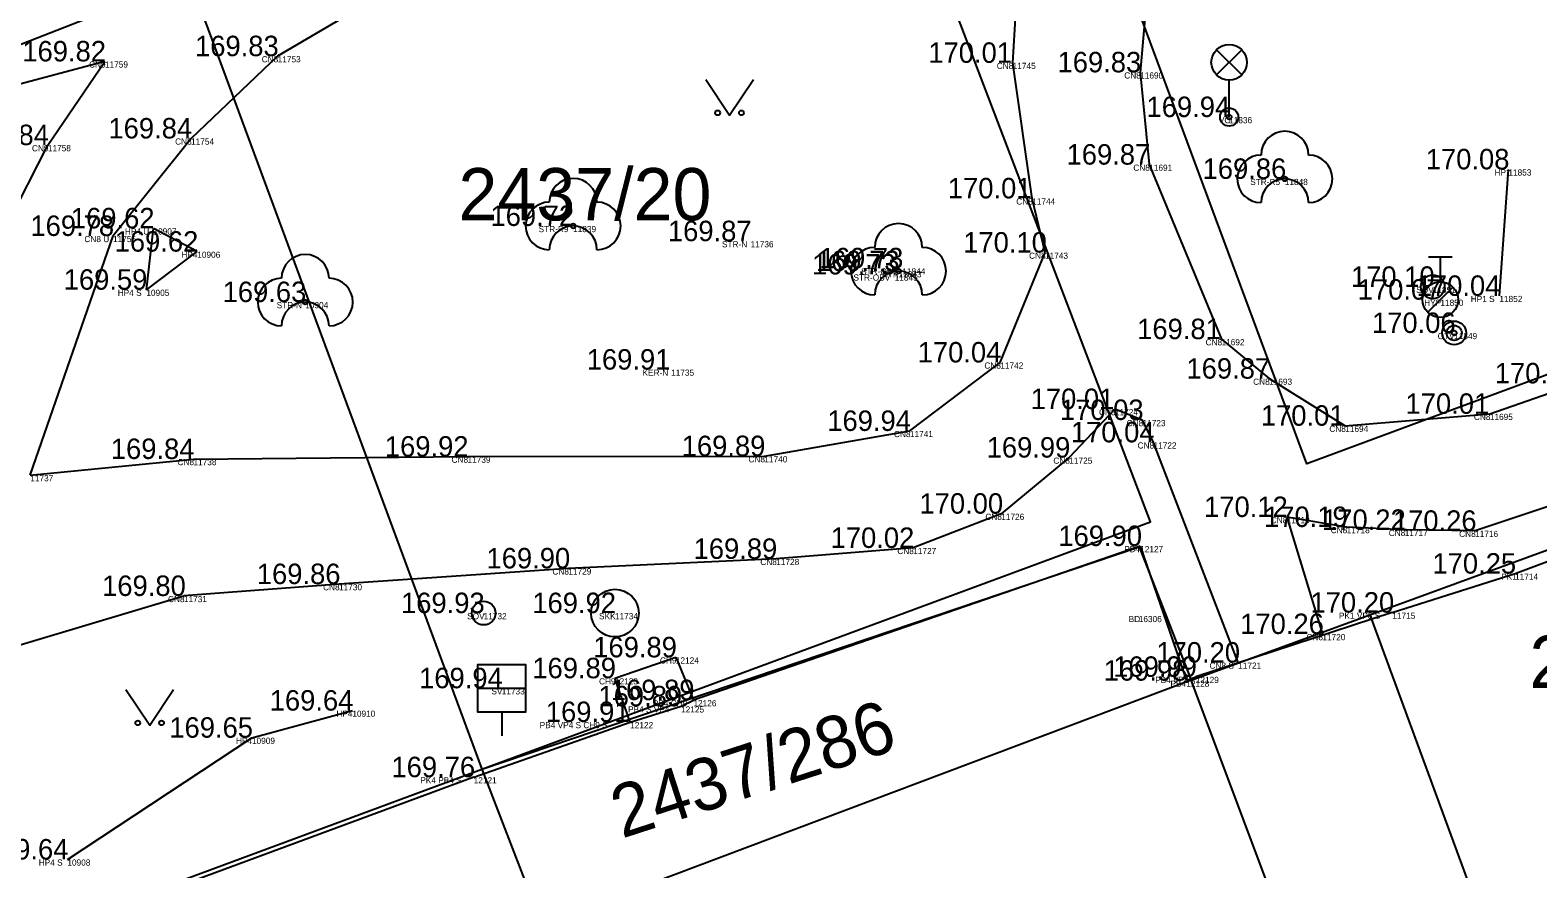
# Model space of a CAD drawing. Extents: x -566117 to -565580, y -1202428 to -1201938.
# Drawn here: x -565973.6 to -565941.91, y -1202276.24 to -1202258.6 of the extents above; entities that cross this region are included whole.
import ezdxf

# ---------------------------------------------------------------- set-up
doc = ezdxf.new("R2010")
doc.units = 0
for name, color, linetype in [('Bod', 7, 'Continuous'), ('CIZÍ_NADZEM', 7, 'Continuous'), ('Implicitní', 7, 'Continuous'), ('Kanalizace', 7, 'Continuous'), ('Katastr', 7, 'Continuous'), ('Kod', 7, 'Continuous'), ('Oplocení', 7, 'Continuous'), ('Voda', 7, 'Continuous'), ('Výška', 7, 'Continuous'), ('ZELEŇ', 7, 'Continuous'), ('ZN_KULTUR', 7, 'Continuous'), ('Zpevněné plohy', 7, 'Continuous'), ('Číslo', 7, 'Continuous')]:
    doc.layers.add(name, color=color, linetype=linetype)

# ---------------------------------------------------------------- blocks, each defined once
blk = doc.blocks.new('A$C69D74C1E')
at = {"layer": 'Katastr'}
for p, q in [((94.11, -187.55), (100.82, -205.7)), ((119.49, -202.46), (128.42, -199.18)), ((115.73, -203.83), (119.49, -202.46)), ((119.49, -202.46), (128.38, -226.66)), ((115.73, -203.83), (102.08, -208.97)), ((125.13, -228.9), (115.73, -203.83)), ((86.57, -210.98), (100.82, -205.7)), ((100.82, -205.7), (102.08, -208.97))]:
    blk.add_line(p, q, dxfattribs=at)
for points in [[(132.68, -193.9), (118.16, -199.28), (104.08, -161.33)], [(100.82, -205.7), (114.88, -200.5), (107.96, -182.37)], [(100.82, -205.7), (114.64, -201.03), (115.73, -203.83)]]:
    blk.add_lwpolyline(points, dxfattribs=at)
for s, p in [('2437/20', (100.33, -194.163)), ('2437/287', (122.843, -203.993))]:
    blk.add_text(s, height=1.1, dxfattribs=at).set_placement(p)
blk.add_text('2437/286', height=1.1, rotation=18, dxfattribs=at).set_placement((103.766, -207.164))
blk = doc.blocks.new('SV')
at = {"layer": 'Voda'}
blk.add_circle((0, 0), 0.25, dxfattribs=at)
blk = doc.blocks.new('OS')
at = {"layer": 'Voda'}
for radius in [0.25, 0.158, 0.05]:
    blk.add_circle((0, 0), radius, dxfattribs=at)
blk = doc.blocks.new('SAV')
at = {"layer": 'Voda'}
blk.add_line((0, -0.5), (0, -1), dxfattribs=at)
for points in [[(-0.5, 0), (-0.5, 0.5), (0.5, 0.5), (0.5, 0)], [(0.5, 0), (0.5, -0.5), (-0.5, -0.5), (-0.5, 0), (0.5, 0)]]:
    blk.add_lwpolyline(points, dxfattribs=at)
blk = doc.blocks.new('STROM')
at = {"layer": 'ZELEŇ'}
blk.add_circle((0, 0), 0.05, dxfattribs=at)
for centre, start, end in [((0, 0.5), 0, 180), ((-0.5, 0), 90, 270), ((0.5, 0), 270, 90), ((0, -0.5), 0, 180)]:
    blk.add_arc(centre, 0.5, start, end, dxfattribs=at)
blk = doc.blocks.new('SAK')
at = {"layer": 'Kanalizace'}
blk.add_circle((0, 0), 0.5, dxfattribs=at)
blk = doc.blocks.new('LA')
at = {"layer": 'CIZÍ_NADZEM'}
for p, q in [((-0.265, 1.415), (0.265, 0.885)), ((-0.265, 0.885), (0.265, 1.415)), ((0, 0), (0, 0.775))]:
    blk.add_line(p, q, dxfattribs=at)
for centre, radius in [((0, 1.15), 0.375), ((0, 0), 0.19), ((0, 0), 0.05)]:
    blk.add_circle(centre, radius, dxfattribs=at)
blk = doc.blocks.new('HYP')
at = {"layer": 'CIZÍ_NADZEM'}
for p, q in [((-0.25, 0.899), (0.25, 0.899)), ((0, 0.375), (0, 0.899)), ((-0.265, -0.265), (0.265, 0.265))]:
    blk.add_line(p, q, dxfattribs=at)
blk.add_circle((0, 0), 0.375, dxfattribs=at)
blk = doc.blocks.new('POINT_DISPLAY')
at = {"layer": 'Implicitní'}
blk.add_line((0, 0), (0, 0), dxfattribs=at)
blk = doc.blocks.new('3.140_2')
at = {"layer": 'ZN_KULTUR'}
blk.add_lwpolyline([(-1, 1.5), (0, 0), (1, 1.5)], dxfattribs=at)
for centre in [(-0.5, 0.1), (0.5, 0.1)]:
    blk.add_circle(centre, 0.1, dxfattribs=at)

msp = doc.modelspace()

# ---------------------------------------------------------------- linework, layer by layer
at = {"layer": 'Oplocení'}
for p, q in [((-565942.39, -1202270.03), (-565937.78, -1202268.28)), ((-565950.27, -1202269.45), (-565959.66, -1202272.69)), ((-565950.27, -1202269.45), (-565949.3, -1202272.28)), ((-565944.97, -1202270.85), (-565942.39, -1202270.03)), ((-565944.97, -1202270.85), (-565949.1, -1202272.2)), ((-565949.3, -1202272.28), (-565949.1, -1202272.2)), ((-565960.99, -1202273.15), (-565959.92, -1202272.82)), ((-565959.92, -1202272.82), (-565959.66, -1202272.69)), ((-565964.28, -1202274.31), (-565960.99, -1202273.15)), ((-565964.28, -1202274.31), (-565972.48, -1202277.34))]:
    msp.add_line(p, q, dxfattribs=at)
at = {"layer": 'ZELEŇ'}
for p, q in [((-565942.72, -1202264.19), (-565942.53, -1202261.53)), ((-565971.16, -1202264.06), (-565971.01, -1202262.77)), ((-565970.09, -1202263.26), (-565971.01, -1202262.77)), ((-565971.16, -1202264.06), (-565970.09, -1202263.26)), ((-565968.94, -1202273.48), (-565966.83, -1202272.91)), ((-565972.82, -1202276.04), (-565968.94, -1202273.48))]:
    msp.add_line(p, q, dxfattribs=at)
at = {"layer": 'Zpevněné plohy'}
for p, q in [((-565949.99, -1202256.29), (-565950.27, -1202259.49)), ((-565952.95, -1202259.29), (-565952.79, -1202256.63)), ((-565965.97, -1202257.72), (-565968.4, -1202259.15)), ((-565978, -1202260.55), (-565971.32, -1202257.92)), ((-565972.03, -1202259.26), (-565974.74, -1202259.98)), ((-565973.23, -1202261.02), (-565972.03, -1202259.26)), ((-565968.4, -1202259.15), (-565970.22, -1202260.88)), ((-565952.54, -1202262.14), (-565952.95, -1202259.29)), ((-565950.27, -1202259.49), (-565950.08, -1202261.43)), ((-565970.22, -1202260.88), (-565971.86, -1202262.93)), ((-565974.08, -1202262.69), (-565973.23, -1202261.02)), ((-565950.08, -1202261.43), (-565948.56, -1202265.1)), ((-565952.27, -1202263.28), (-565952.54, -1202262.14)), ((-565973.6, -1202267.96), (-565971.86, -1202262.93)), ((-565953.21, -1202265.59), (-565952.27, -1202263.28)), ((-565948.56, -1202265.1), (-565947.56, -1202265.93)), ((-565955.11, -1202267.03), (-565953.21, -1202265.59)), ((-565947.56, -1202265.93), (-565945.96, -1202266.92)), ((-565942.92, -1202266.67), (-565941.08, -1202266.03)), ((-565950.8, -1202266.57), (-565951.76, -1202267.59)), ((-565950.22, -1202266.8), (-565950.8, -1202266.57)), ((-565949.99, -1202267.27), (-565950.22, -1202266.8)), ((-565945.96, -1202266.92), (-565942.92, -1202266.67)), ((-565958.17, -1202267.56), (-565955.11, -1202267.03)), ((-565964.41, -1202267.57), (-565958.17, -1202267.56)), ((-565948.21, -1202271.9), (-565949.99, -1202267.27)), ((-565938.04, -1202267.39), (-565943.23, -1202269.13)), ((-565973.6, -1202267.96), (-565970.17, -1202267.62)), ((-565970.17, -1202267.62), (-565964.41, -1202267.57)), ((-565951.76, -1202267.59), (-565953.19, -1202268.77)), ((-565953.19, -1202268.77), (-565955.04, -1202269.49)), ((-565947.19, -1202268.84), (-565946.44, -1202271.3)), ((-565945.93, -1202269.05), (-565947.19, -1202268.84)), ((-565944.71, -1202269.11), (-565945.93, -1202269.05)), ((-565943.23, -1202269.13), (-565944.71, -1202269.11)), ((-565957.92, -1202269.72), (-565962.29, -1202269.92)), ((-565955.04, -1202269.49), (-565957.92, -1202269.72)), ((-565962.29, -1202269.92), (-565967.11, -1202270.25)), ((-565967.11, -1202270.25), (-565970.37, -1202270.5)), ((-565961.31, -1202272.23), (-565960.03, -1202271.79)), ((-565960.03, -1202271.79), (-565959.66, -1202272.69)), ((-565960.99, -1202273.15), (-565961.31, -1202272.23))]:
    msp.add_line(p, q, dxfattribs=at)
msp.add_lwpolyline([(-565976.15, -1202272.67), (-565974.64, -1202271.77), (-565970.37, -1202270.5)], dxfattribs=at)

# ---------------------------------------------------------------- block references
at = {"layer": 'Bod'}
for p in [(-565972.03, -1202259.26), (-565968.4, -1202259.15), (-565952.95, -1202259.29), (-565950.27, -1202259.49), (-565948.4, -1202260.43), (-565970.22, -1202260.88), (-565973.23, -1202261.02), (-565950.08, -1202261.43), (-565942.53, -1202261.53), (-565947.23, -1202261.73), (-565952.54, -1202262.14), (-565971.01, -1202262.77), (-565962.19, -1202262.72), (-565971.86, -1202262.93), (-565958.46, -1202263.04), (-565970.09, -1202263.26), (-565952.27, -1202263.28), (-565955.43, -1202263.74), (-565955.35, -1202263.67), (-565955.27, -1202263.61), (-565971.16, -1202264.06), (-565944.12, -1202264), (-565967.82, -1202264.32), (-565943.96, -1202264.27), (-565942.72, -1202264.19), (-565943.67, -1202264.97), (-565948.56, -1202265.1), (-565953.21, -1202265.59), (-565960.13, -1202265.74), (-565947.56, -1202265.93), (-565950.8, -1202266.57), (-565950.22, -1202266.8), (-565945.96, -1202266.92), (-565942.92, -1202266.67), (-565955.11, -1202267.03), (-565958.17, -1202267.56), (-565949.99, -1202267.27), (-565970.17, -1202267.62), (-565964.41, -1202267.57), (-565951.76, -1202267.59), (-565973.6, -1202267.96), (-565953.19, -1202268.77), (-565947.19, -1202268.84), (-565945.93, -1202269.05), (-565944.71, -1202269.11), (-565943.23, -1202269.13), (-565950.27, -1202269.45), (-565957.92, -1202269.72), (-565955.04, -1202269.49), (-565962.29, -1202269.92), (-565942.39, -1202270.03), (-565967.11, -1202270.25), (-565970.37, -1202270.5), (-565964.07, -1202270.86), (-565961.31, -1202270.86), (-565950.3, -1202270.92), (-565944.97, -1202270.85), (-565946.44, -1202271.3), (-565960.03, -1202271.79), (-565948.21, -1202271.9), (-565961.31, -1202272.23), (-565949.3, -1202272.28), (-565949.1, -1202272.2), (-565963.69, -1202272.44), (-565966.83, -1202272.91), (-565959.92, -1202272.82), (-565959.66, -1202272.69), (-565960.99, -1202273.15), (-565968.94, -1202273.48), (-565964.28, -1202274.31), (-565972.82, -1202276.04)]:
    msp.add_blockref('POINT_DISPLAY', p, dxfattribs=at)
at = {"layer": 'CIZÍ_NADZEM'}
for name, p in [('LA', (-565948.4, -1202260.43)), ('HYP', (-565943.96, -1202264.27))]:
    msp.add_blockref(name, p, dxfattribs=at)
at = {"layer": 'Implicitní'}
msp.add_blockref('A$C69D74C1E', (-566064.93, -1202068.44), dxfattribs=at)
at = {"layer": 'Kanalizace'}
msp.add_blockref('SAK', (-565961.31, -1202270.86), dxfattribs=at)
at = {"layer": 'Voda'}
for name, p in [('SV', (-565944.12, -1202264)), ('OS', (-565943.67, -1202264.97)), ('SV', (-565964.07, -1202270.86))]:
    msp.add_blockref(name, p, dxfattribs=at)
at = {"layer": 'Voda', "xscale": 0.9999953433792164, "yscale": 0.9999953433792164}
msp.add_blockref('SAV', (-565963.69, -1202272.44), dxfattribs=at)
at = {"layer": 'ZELEŇ'}
for p in [(-565947.23, -1202261.73), (-565962.19, -1202262.72), (-565955.35, -1202263.67), (-565967.82, -1202264.32)]:
    msp.add_blockref('STROM', p, dxfattribs=at)
at = {"layer": 'ZN_KULTUR', "xscale": 0.5, "yscale": 0.5}
for p in [(-565958.901, -1202260.391), (-565971.09, -1202273.218)]:
    msp.add_blockref('3.140_2', p, dxfattribs=at)

# ---------------------------------------------------------------- texts
at = {"layer": 'Kod'}
for s, p in [('CN9', (-565972.365, -1202259.39)), ('CN8', (-565968.735, -1202259.28)), ('CN8', (-565953.285, -1202259.42)), ('CN8', (-565950.605, -1202259.62)), ('VO', (-565948.616, -1202260.56)), ('CN8', (-565970.555, -1202261.01)), ('CN9', (-565973.565, -1202261.15)), ('CN8', (-565950.415, -1202261.56)), ('HP1', (-565942.822, -1202261.66)), ('STR-R5', (-565947.957, -1202261.86)), ('CN8', (-565952.875, -1202262.27)), ('HP4 U', (-565971.612, -1202262.9)), ('STR-R9', (-565962.915, -1202262.85)), ('CN8 U', (-565972.462, -1202263.06)), ('STR-N', (-565959.061, -1202263.17)), ('HP4', (-565970.425, -1202263.39)), ('CN8', (-565952.605, -1202263.41)), ('STR-OBV', (-565956.297, -1202263.87)), ('STR-OBV', (-565956.137, -1202263.74)), ('STR', (-565955.691, -1202263.8)), ('HP4 S', (-565971.762, -1202264.19)), ('SOV', (-565944.467, -1202264.13)), ('STR-N', (-565968.421, -1202264.45)), ('HYP', (-565944.301, -1202264.4)), ('HP1 S', (-565943.322, -1202264.32)), ('OTV', (-565944.017, -1202265.1)), ('CN8', (-565948.895, -1202265.23)), ('CN8', (-565953.545, -1202265.72)), ('KER-N', (-565960.731, -1202265.87)), ('CN8', (-565947.895, -1202266.06)), ('CN8', (-565951.135, -1202266.7)), ('CN8', (-565950.555, -1202266.93)), ('CN8', (-565946.295, -1202267.05)), ('CN8', (-565943.255, -1202266.8)), ('CN8', (-565955.445, -1202267.16)), ('CN8', (-565958.505, -1202267.69)), ('CN8', (-565950.325, -1202267.4)), ('CN8', (-565970.505, -1202267.75)), ('CN8', (-565964.745, -1202267.7)), ('CN8', (-565952.095, -1202267.72)), ('CN8', (-565953.525, -1202268.9)), ('CN8', (-565947.525, -1202268.97)), ('CN8', (-565946.265, -1202269.18)), ('CN8', (-565945.045, -1202269.24)), ('CN8', (-565943.565, -1202269.26)), ('PB4', (-565950.605, -1202269.58)), ('CN8', (-565958.255, -1202269.85)), ('CN8', (-565955.375, -1202269.62)), ('CN8', (-565962.625, -1202270.05)), ('PK1', (-565942.682, -1202270.16)), ('CN8', (-565967.445, -1202270.38)), ('CN8', (-565970.705, -1202270.63)), ('SOV', (-565964.417, -1202270.99)), ('SKK', (-565961.645, -1202270.99)), ('BD', (-565950.513, -1202271.05)), ('PK1 VP8 S', (-565946.092, -1202270.98)), ('CN8', (-565946.775, -1202271.43)), ('CH9', (-565960.365, -1202271.92)), ('CN8 S', (-565948.812, -1202272.03)), ('CH9', (-565961.645, -1202272.36)), ('PB4 VP8', (-565949.955, -1202272.33)), ('PB4', (-565949.635, -1202272.41)), ('SV', (-565963.907, -1202272.57)), ('HP4', (-565967.165, -1202273.04)), ('PB4 S VP4', (-565961.035, -1202272.95)), ('PB4 CH9', (-565960.515, -1202272.82)), ('PB4 VP4 S CH9 S', (-565962.892, -1202273.28)), ('HP4', (-565969.275, -1202273.61)), ('PK4 PB4 S', (-565965.402, -1202274.44)), ('HP4 S', (-565973.422, -1202276.17))]:
    msp.add_text(s, height=0.13, dxfattribs=at).set_placement(p)
at = {"layer": 'Výška'}
for s, p in [('169.82 ', (-565973.767, -1202259.26)), ('169.83 ', (-565970.137, -1202259.15)), ('170.01 ', (-565954.723, -1202259.29)), ('169.83 ', (-565952.007, -1202259.49)), ('169.94 ', (-565950.137, -1202260.43)), ('169.84 ', (-565974.967, -1202261.02)), ('169.84 ', (-565971.957, -1202260.88)), ('169.87 ', (-565951.817, -1202261.43)), ('170.08 ', (-565944.267, -1202261.53)), ('169.86 ', (-565948.958, -1202261.73)), ('170.01 ', (-565954.313, -1202262.14)), ('169.62 ', (-565972.747, -1202262.77)), ('169.72 ', (-565963.927, -1202262.72)), ('169.78 ', (-565973.597, -1202262.93)), ('169.87 ', (-565960.197, -1202263.04)), ('169.62 ', (-565971.827, -1202263.26)), ('170.10 ', (-565953.99, -1202263.28)), ('169.73 ', (-565957.167, -1202263.74)), ('169.73 ', (-565957.087, -1202263.67)), ('169.73 ', (-565957.007, -1202263.61)), ('169.59 ', (-565972.897, -1202264.06)), ('170.10 ', (-565945.84, -1202264)), ('170.04 ', (-565944.457, -1202264.19)), ('169.63 ', (-565969.557, -1202264.32)), ('170.07 ', (-565945.697, -1202264.27)), ('169.81 ', (-565950.333, -1202265.1)), ('170.06 ', (-565945.398, -1202264.97)), ('169.91 ', (-565961.903, -1202265.74)), ('170.04 ', (-565954.947, -1202265.59)), ('169.87 ', (-565949.297, -1202265.93)), ('170.08 ', (-565942.817, -1202266.03)), ('170.01 ', (-565952.573, -1202266.57)), ('170.01 ', (-565944.693, -1202266.67)), ('169.94 ', (-565956.847, -1202267.03)), ('170.03 ', (-565951.957, -1202266.8)), ('170.01 ', (-565947.733, -1202266.92)), ('170.04 ', (-565951.727, -1202267.27)), ('169.84 ', (-565971.907, -1202267.62)), ('169.92 ', (-565966.147, -1202267.57)), ('169.89 ', (-565959.907, -1202267.56)), ('169.99 ', (-565953.497, -1202267.59)), ('170.00 ', (-565954.91, -1202268.77)), ('170.12 ', (-565948.927, -1202268.84)), ('170.19 ', (-565947.667, -1202269.05)), ('170.22 ', (-565946.447, -1202269.11)), ('170.26 ', (-565944.958, -1202269.13)), ('170.02 ', (-565956.777, -1202269.49)), ('169.90 ', (-565951.99, -1202269.45)), ('169.89 ', (-565959.657, -1202269.72)), ('169.90 ', (-565964.01, -1202269.92)), ('170.25 ', (-565944.127, -1202270.03)), ('169.80 ', (-565972.09, -1202270.5)), ('169.86 ', (-565968.838, -1202270.25)), ('170.20 ', (-565946.69, -1202270.85)), ('169.93 ', (-565965.807, -1202270.86)), ('169.92 ', (-565963.047, -1202270.86)), ('170.26 ', (-565948.168, -1202271.3)), ('169.89 ', (-565961.767, -1202271.79)), ('170.20 ', (-565949.93, -1202271.9)), ('169.89 ', (-565963.047, -1202272.23)), ('169.98 ', (-565951.037, -1202272.28)), ('169.99 ', (-565950.837, -1202272.2)), ('169.94 ', (-565965.427, -1202272.44)), ('169.89 ', (-565961.397, -1202272.69)), ('169.64 ', (-565968.567, -1202272.91)), ('169.89 ', (-565961.657, -1202272.82)), ('169.91 ', (-565962.763, -1202273.15)), ('169.65 ', (-565970.677, -1202273.48)), ('169.76 ', (-565966.008, -1202274.31)), ('169.64 ', (-565974.557, -1202276.04))]:
    msp.add_text(s, height=0.43, dxfattribs=at).set_placement(p)
at = {"layer": 'Číslo'}
for s, p in [('11759', (-565972.03, -1202259.39)), ('11753', (-565968.4, -1202259.28)), ('11745', (-565952.95, -1202259.42)), ('11690', (-565950.27, -1202259.62)), ('11836', (-565948.4, -1202260.56)), ('11754', (-565970.22, -1202261.01)), ('11758', (-565973.23, -1202261.15)), ('11691', (-565950.08, -1202261.56)), ('11853', (-565942.53, -1202261.66)), ('11848', (-565947.23, -1202261.86)), ('11744', (-565952.54, -1202262.27)), ('10907', (-565971.01, -1202262.9)), ('11839', (-565962.19, -1202262.85)), ('11755', (-565971.86, -1202263.06)), ('11736', (-565958.46, -1202263.17)), ('10906', (-565970.09, -1202263.39)), ('11743', (-565952.27, -1202263.41)), ('11845', (-565955.43, -1202263.87)), ('11843', (-565955.35, -1202263.8)), ('11844', (-565955.27, -1202263.74)), ('10905', (-565971.16, -1202264.19)), ('11851', (-565944.12, -1202264.13)), ('10904', (-565967.82, -1202264.45)), ('11850', (-565943.96, -1202264.4)), ('11852', (-565942.72, -1202264.32)), ('11849', (-565943.67, -1202265.1)), ('11692', (-565948.56, -1202265.23)), ('11742', (-565953.21, -1202265.72)), ('11735', (-565960.13, -1202265.87)), ('11693', (-565947.56, -1202266.06)), ('11724', (-565950.8, -1202266.7)), ('11723', (-565950.22, -1202266.93)), ('11694', (-565945.96, -1202267.05)), ('11695', (-565942.92, -1202266.8)), ('11741', (-565955.11, -1202267.16)), ('11740', (-565958.17, -1202267.69)), ('11722', (-565949.99, -1202267.4)), ('11738', (-565970.17, -1202267.75)), ('11739', (-565964.41, -1202267.7)), ('11725', (-565951.76, -1202267.72)), ('11737', (-565973.6, -1202268.09)), ('11726', (-565953.19, -1202268.9)), ('11719', (-565947.19, -1202268.97)), ('11718', (-565945.93, -1202269.18)), ('11717', (-565944.71, -1202269.24)), ('11716', (-565943.23, -1202269.26)), ('12127', (-565950.27, -1202269.58)), ('11728', (-565957.92, -1202269.85)), ('11727', (-565955.04, -1202269.62)), ('11729', (-565962.29, -1202270.05)), ('11714', (-565942.39, -1202270.16)), ('11730', (-565967.11, -1202270.38)), ('11731', (-565970.37, -1202270.63)), ('11732', (-565964.07, -1202270.99)), ('11734', (-565961.31, -1202270.99)), ('16306', (-565950.3, -1202271.05)), ('11715', (-565944.97, -1202270.98)), ('11720', (-565946.44, -1202271.43)), ('12124', (-565960.03, -1202271.92)), ('11721', (-565948.21, -1202272.03)), ('12123', (-565961.31, -1202272.36)), ('12128', (-565949.3, -1202272.41)), ('12129', (-565949.1, -1202272.33)), ('11733', (-565963.69, -1202272.57)), ('10910', (-565966.83, -1202273.04)), ('12125', (-565959.92, -1202272.95)), ('12126', (-565959.66, -1202272.82)), ('12122', (-565960.99, -1202273.28)), ('10909', (-565968.94, -1202273.61)), ('12121', (-565964.28, -1202274.44)), ('10908', (-565972.82, -1202276.17))]:
    msp.add_text(s, height=0.13, dxfattribs=at).set_placement(p)

doc.saveas('drawing.dxf')
